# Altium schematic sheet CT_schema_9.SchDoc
size 277 x 170 mm
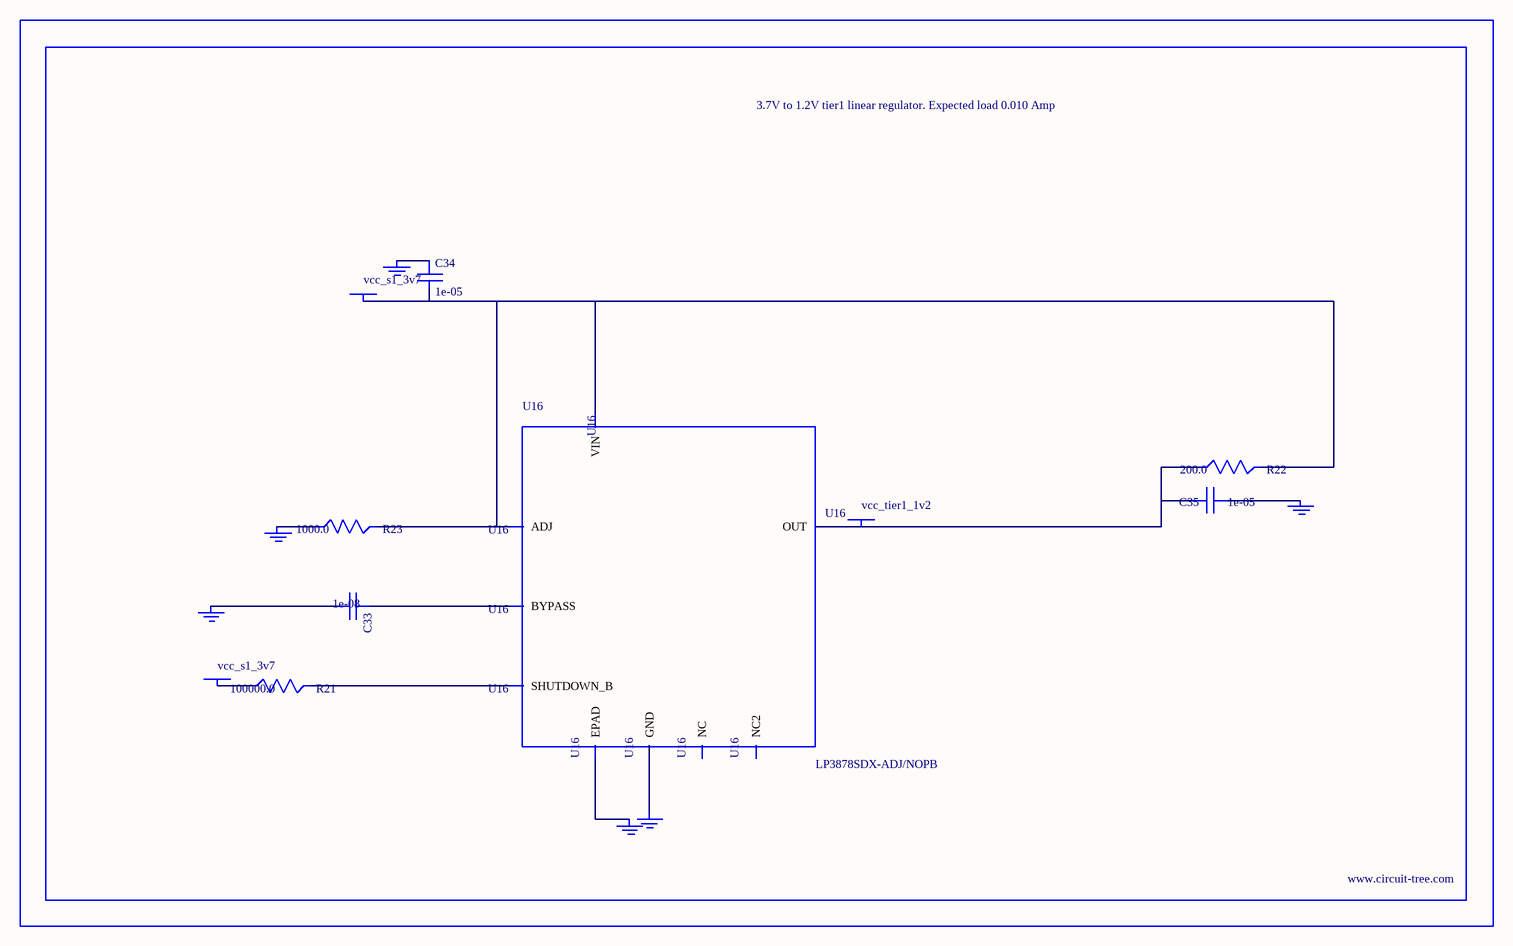
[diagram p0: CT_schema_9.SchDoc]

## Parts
BORDER8  (no value)
C33  1e-08  [C0402]
C34  1e-05  [C0805]
C35  1e-05  [C0805]
GND_INSTANCE_8_0  (no value)
GND_INSTANCE_8_1  (no value)
GND_INSTANCE_8_2  (no value)
GND_INSTANCE_8_3  (no value)
GND_INSTANCE_8_4  (no value)
GND_INSTANCE_8_5  (no value)
POWER_INSTANCE_8_0  vcc_s1_3v7
POWER_INSTANCE_8_1  vcc_s1_3v7
POWER_INSTANCE_8_2  vcc_tier1_1v2
R21  100000.0  [R0603]
R22  200.0  [R0603]
R23  1000.0  [R0603]
U16  LP3878SDX-ADJ/NOPB  [WSON-8]

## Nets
NetC33_1: C33.1 U16.1(BYPASS)
NetC33_2: C33.2 GND_INSTANCE_8_0.0(GND)
NetC34_1: C34.1 GND_INSTANCE_8_1.0(GND)
NetC34_2: C34.2 POWER_INSTANCE_8_0.0(PWR) R22.2 R23.2 U16.4(VIN) U16.6(ADJ)
NetC35_1: C35.1 GND_INSTANCE_8_2.0(GND)
NetC35_2: C35.2 POWER_INSTANCE_8_2.0(PWR) R22.1 U16.5(OUT)
NetGND_INSTANCE_8_3_0: GND_INSTANCE_8_3.0(GND) R23.1
NetGND_INSTANCE_8_4_0: GND_INSTANCE_8_4.0(GND) U16.PAD(EPAD)
NetGND_INSTANCE_8_5_0: GND_INSTANCE_8_5.0(GND) U16.3(GND)
NetPOWER_INSTANCE_8_1_0: POWER_INSTANCE_8_1.0(PWR) R21.1
NetR21_2: R21.2 U16.8(SHUTDOWN_B)

Not connected (* = marked no-connect by the designer): U16 2(NC) 7(NC2)

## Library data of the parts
BORDER8 = BORDER_PAGE8
C33 = C0402C103K3RAC
C34 = C0805C106K8RACTU
C35 = GRM219R60J106ME19D
GND_INSTANCE_8_0-GND_INSTANCE_8_5 = GND
POWER_INSTANCE_8_0-POWER_INSTANCE_8_2 = PWR
R21 = RC0603JR-07100KL
R22 = RC0603JR-07200RL
R23 = RC0603JR-071KL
